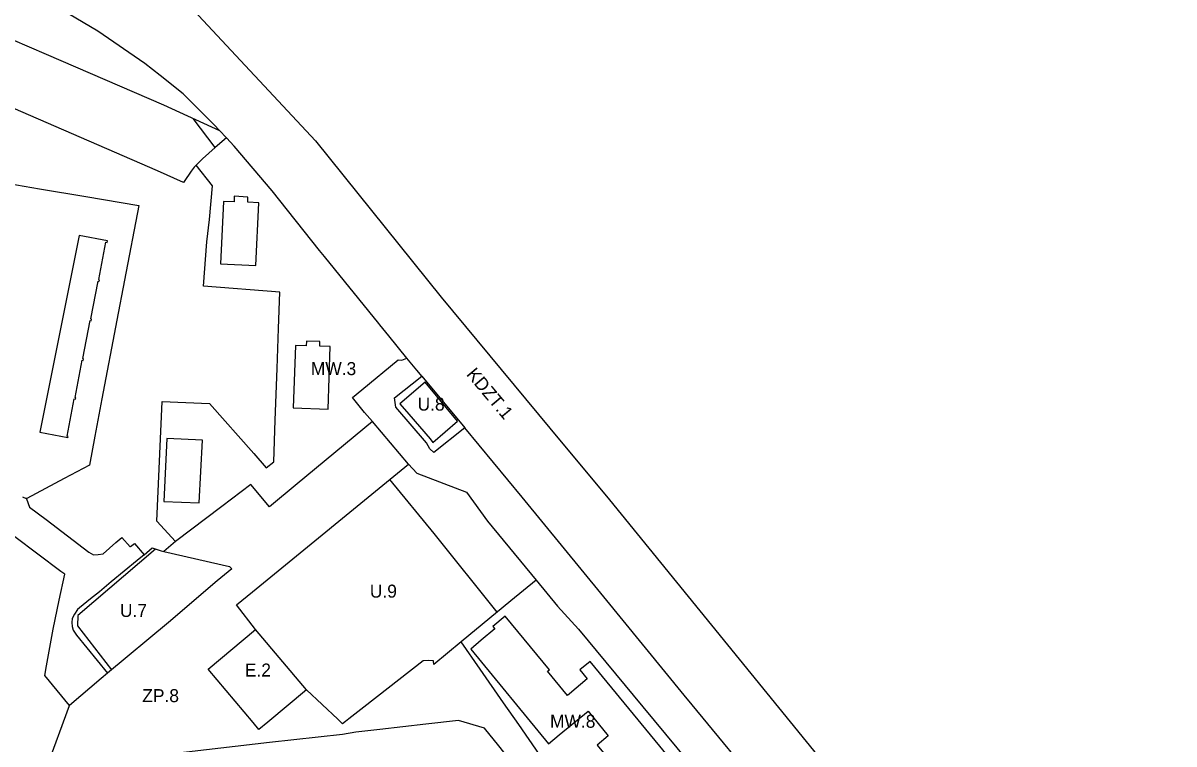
# Model space of a CAD drawing. Extents: x 7428689 to 7430424, y 5549101 to 5550539.
# Drawn here: x 7429899 to 7430341.5, y 5549954.9 to 5550232.1 of the extents above; entities that cross this region are included whole.
import ezdxf

# ---------------------------------------------------------------- set-up
doc = ezdxf.new("R2010")
doc.units = 0
for name, color, linetype in [('linie rozgraniczające', 7, 'Continuous'), ('nieprzekraczalne linie zabudowy', 7, 'Continuous'), ('obowiazujace linie zabudowy', 7, 'Continuous'), ('przeznaczenia terenów', 7, 'Continuous')]:
    doc.layers.add(name, color=color, linetype=linetype)

msp = doc.modelspace()

# ---------------------------------------------------------------- linework, layer by layer
at = {"layer": 'linie rozgraniczające'}
for points in [[(7429816.83, 5550334.12), (7429833.34, 5550323.51), (7429855.56, 5550306.27), (7429881.93, 5550290.04), (7429926.89, 5550263.18), (7429964.68, 5550236.86), (7430011.43, 5550186.87), (7430059.81, 5550126.71), (7430101.57, 5550076.38), (7430124.52, 5550048.84), (7430239.35, 5549907.74), (7430243.53, 5549902.67), (7430275.28, 5549864.05), (7430299.52, 5549835.73), (7430341.5, 5549786.7)], [(7429974.55, 5550190.8), (7429972.48, 5550192.99), (7429960.54, 5550204.88), (7429951.74, 5550211.88), (7429945.88, 5550216.54), (7429927.77, 5550228.95), (7429913.66, 5550237.27), (7429901.94, 5550242.49), (7429897.67, 5550244.65), (7429884.92, 5550250.06), (7429879.58, 5550252.11), (7429872.23, 5550253.14), (7429869.16, 5550253.7), (7429844.49, 5550258.25), (7429843.75, 5550257.92)], [(7429840.08, 5550249.7), (7429841.04, 5550249.22), (7429881.63, 5550231.45), (7429907.93, 5550220.14), (7429952.95, 5550200.66), (7429974.55, 5550190.8)], [(7429965.52, 5550177.42), (7429964.79, 5550176.7), (7429963.7, 5550175.14), (7429960.95, 5550171.21), (7429960.63, 5550170.77), (7429960.63, 5550170.77), (7429950.64, 5550175.25), (7429868.83, 5550210.74), (7429830.34, 5550227.16)], [(7429977.22, 5550187.97), (7429974.55, 5550190.8)], [(7429977.22, 5550187.97), (7429972.92, 5550184.19), (7429968.01, 5550179.86), (7429965.52, 5550177.42)], [(7430046.57, 5550103.3), (7430039.64, 5550111.84), (7430036.18, 5550116.11), (7430035.74, 5550116.65), (7430014.87, 5550142.37), (7430013, 5550144.71), (7429994.83, 5550167.53), (7429980.2, 5550184.81), (7429977.22, 5550187.97)], [(7429957.63, 5550032.81), (7429950.45, 5550040.61), (7429952.55, 5550086.64), (7429970.64, 5550085.84), (7429987.68, 5550066.58), (7429992.49, 5550061.14), (7429995.41, 5550063.45), (7429995.98, 5550079.47), (7429996.68, 5550099.33), (7429997.23, 5550114.66), (7429997.72, 5550128.64), (7429968.32, 5550130.9), (7429969.69, 5550147.97), (7429970.67, 5550156.63), (7429971.78, 5550169.49), (7429965.52, 5550177.42)], [(7429890.65, 5550170.87), (7429905.27, 5550168.41), (7429923.12, 5550165.39), (7429943.47, 5550161.94), (7429938, 5550133.23), (7429935.08, 5550117.93), (7429929.3, 5550087.66), (7429926.57, 5550073.31), (7429924.49, 5550062.1), (7429914.84, 5550057), (7429900.44, 5550049.34), (7429900.22, 5550049.26)], [(7430033.32, 5550078.87), (7430030.31, 5550082.41), (7430025.64, 5550088.17), (7430029.25, 5550091.14), (7430043.27, 5550102.67), (7430044.69, 5550102.51), (7430046.57, 5550103.3)], [(7430052.35, 5550096.35), (7430051.86, 5550096.93), (7430050.4, 5550098.69), (7430046.57, 5550103.3)], [(7430068.9, 5550076.43), (7430056.93, 5550066.95), (7430055.46, 5550068.36), (7430054.1, 5550070.73), (7430042.32, 5550084.38), (7430041.85, 5550088.03), (7430052.35, 5550096.35)], [(7430052.35, 5550096.35), (7430068.9, 5550076.43)], [(7430033.32, 5550078.87), (7430004.41, 5550054.97), (7429993.75, 5550046.17), (7429986.56, 5550054.72), (7429975.4, 5550046.27), (7429957.63, 5550032.81)], [(7430047.16, 5550062.55), (7430033.32, 5550078.87)], [(7430258.04, 5549845.58), (7430248.2, 5549857.63), (7430222.19, 5549889.25), (7430215.68, 5549897.16), (7430184.53, 5549935.61), (7430156.23, 5549969.99), (7430153.13, 5549973.76), (7430122.35, 5550011.53), (7430090.9, 5550049.78), (7430068.9, 5550076.43)], [(7429988.39, 5549998.93), (7429981.1, 5550008.49), (7429987.18, 5550013.47), (7430047.16, 5550062.55)], [(7430047.16, 5550062.55), (7430050.46, 5550059.05), (7430069.46, 5550051.75), (7430077.53, 5550040.58), (7430096.23, 5550017.94)], [(7429898.75, 5550050.01), (7429900.22, 5550049.26)], [(7429900.22, 5550049.26), (7429900.36, 5550049.19), (7429901.43, 5550046.02), (7429907.84, 5550041.19), (7429924.25, 5550028.63), (7429926.03, 5550027.7), (7429927.88, 5550027.77), (7429929.74, 5550028.1), (7429934.63, 5550032.4), (7429936.95, 5550034.32), (7429940.14, 5550030.72), (7429940.33, 5550030.88), (7429941.86, 5550032.07), (7429945.57, 5550027.67)], [(7429916.81, 5549969.68), (7429907.37, 5549981.28), (7429907.97, 5549984.97), (7429910.62, 5549999.1), (7429912.84, 5550010.27), (7429915.01, 5550020.22), (7429913.54, 5550021.3), (7429904.69, 5550027.9), (7429895.81, 5550034.62)], [(7429945.57, 5550027.67), (7429948.67, 5550030.31), (7429952.06, 5550029.17), (7429952.07, 5550029.17), (7429953.13, 5550028.93)], [(7429957.63, 5550032.81), (7429953.13, 5550028.93)], [(7429945.57, 5550027.67), (7429942.87, 5550025.42), (7429932.92, 5550017.22), (7429928.45, 5550013.44), (7429924.96, 5550010.69), (7429920.75, 5550007.3), (7429919.93, 5550006.59), (7429918.79, 5550004.89), (7429917.94, 5550003.17), (7429917.76, 5550001.64), (7429917.86, 5550000.05), (7429918.21, 5549998.68), (7429919.59, 5549996.77), (7429931.46, 5549982.14)], [(7429953.13, 5550028.93), (7429978.42, 5550023.18), (7429979.28, 5550022.22), (7429973.68, 5550017.66), (7429954.88, 5550001.69), (7429931.46, 5549982.14)], [(7430096.23, 5550017.94), (7430086.57, 5550010), (7430067.39, 5549994.23)], [(7430096.23, 5550017.94), (7430104.53, 5550007.9), (7430112.53, 5549999.04), (7430137.26, 5549969.22), (7430168.39, 5549931.68), (7430168.64, 5549931.38)], [(7430007.96, 5549975.79), (7429993.05, 5549963.37), (7429989.68, 5549960.56), (7429987.51, 5549963.14), (7429970.23, 5549983.76), (7429988.39, 5549998.93)], [(7430007.96, 5549975.79), (7429988.39, 5549998.93)], [(7430067.39, 5549994.23), (7430056.95, 5549985.45), (7430056.79, 5549986.97), (7430054.88, 5549987.05), (7430052.78, 5549986.95), (7430029.98, 5549969.1), (7430024.28, 5549964.64), (7430022.92, 5549963.57), (7430021.85, 5549962.74), (7430020.01, 5549964.46), (7430007.96, 5549975.79)], [(7430168.64, 5549931.38), (7430168.37, 5549930.61), (7430163.03, 5549927.09), (7430147.1, 5549927.18), (7430123.56, 5549927.32), (7430113.91, 5549933.66), (7430105.97, 5549938.87), (7430097.56, 5549950.93), (7430089.55, 5549962.42), (7430083.75, 5549970.74), (7430074.73, 5549983.7), (7430067.39, 5549994.23)], [(7429931.46, 5549982.14), (7429929.03, 5549980.11), (7429916.81, 5549969.68)], [(7429908.04, 5549945.59), (7429916.81, 5549969.68)], [(7430085.82, 5549949.33), (7430081.94, 5549954.22), (7430076.43, 5549961.08), (7430066.36, 5549963.92), (7430053.83, 5549962.51), (7430036.17, 5549960.52), (7430026.92, 5549959.51), (7430021.76, 5549958.62), (7429993.81, 5549955.51), (7429956.35, 5549951.19), (7429926.16, 5549947.7), (7429925.68, 5549947.31), (7429914.12, 5549946.03), (7429908.04, 5549945.59)]]:
    msp.add_lwpolyline(points, dxfattribs=at)
at = {"layer": 'nieprzekraczalne linie zabudowy'}
for points in [[(7429972.92, 5550184.19), (7429964.42, 5550195.42)], [(7430066.07, 5550079.05), (7430053.61, 5550094.05), (7430043.8, 5550085.68), (7430047.3, 5550081.67), (7430055.47, 5550072.21), (7430056.59, 5550070.89), (7430066.07, 5550079.05)], [(7430081.37, 5550005.72), (7430081.32, 5550005.68), (7430057.03, 5550035.86), (7430039.99, 5550056.68)], [(7429949.9, 5550029.9), (7429920.01, 5550004.29), (7429919.93, 5550000.31), (7429933.01, 5549983.44)]]:
    msp.add_lwpolyline(points, dxfattribs=at)
at = {"layer": 'obowiazujace linie zabudowy'}
for points in [[(7429976.05, 5550163.5), (7429974.92, 5550139.5), (7429988.52, 5550138.86), (7429989.62, 5550162.94), (7429985.45, 5550163.23), (7429985.46, 5550165.2), (7429980.21, 5550165.49), (7429980.19, 5550163.41), (7429976.05, 5550163.5)], [(7429905.44, 5550074.79), (7429916.22, 5550072.75), (7429916.31, 5550073.21), (7429915.99, 5550073.27), (7429918.7, 5550087.59), (7429919.21, 5550087.49), (7429919.32, 5550088.05), (7429918.99, 5550088.11), (7429921.71, 5550102.48), (7429922.13, 5550102.41), (7429922.25, 5550103.06), (7429922, 5550103.11), (7429924.77, 5550117.71), (7429925.24, 5550117.62), (7429925.37, 5550118.27), (7429925.1, 5550118.32), (7429927.85, 5550132.83), (7429928.2, 5550132.76), (7429928.33, 5550133.43), (7429928.12, 5550133.47), (7429930.84, 5550147.84), (7429931.35, 5550147.75), (7429931.48, 5550148.42), (7429920.61, 5550150.48), (7429905.44, 5550074.79)], [(7430017.14, 5550107.77), (7430013.11, 5550107.89), (7430013.1, 5550109.61), (7430007.93, 5550109.83), (7430007.83, 5550108.04), (7430003.69, 5550108.13), (7430002.91, 5550084.17), (7430016.37, 5550083.64), (7430017.14, 5550107.77)], [(7429954.25, 5550072.37), (7429953.09, 5550048.21), (7429966.67, 5550047.64), (7429967.97, 5550071.75), (7429954.25, 5550072.37)], [(7430100.69, 5549982.89), (7430101.39, 5549983.47), (7430084.39, 5550004.03), (7430079.67, 5550000.13), (7430080.43, 5549999.23), (7430075.15, 5549994.87), (7430071.11, 5549991.43), (7430101.06, 5549955.06), (7430105.13, 5549958.43), (7430116.3, 5549967.6), (7430124.01, 5549958.08), (7430119.73, 5549954.55), (7430140.42, 5549929.45), (7430144.69, 5549932.97), (7430149.92, 5549937.27), (7430150.46, 5549936.61), (7430155.07, 5549940.41), (7430117, 5549986.63), (7430113.09, 5549983.47), (7430115.92, 5549979.93), (7430109.04, 5549974.18), (7430108.31, 5549973.63), (7430100.69, 5549982.89)]]:
    msp.add_lwpolyline(points, dxfattribs=at)

# ---------------------------------------------------------------- texts
at = {"layer": 'przeznaczenia terenów'}
for s, p in [('MW.3', (7430009.64, 5550096.75)), ('U.8', (7430050.68, 5550083.1)), ('U.9', (7430032.33, 5550011.2)), ('U.7', (7429936.25, 5550003.77)), ('E.2', (7429984.27, 5549980.87)), ('ZP.8', (7429944.83, 5549971.03)), ('MW.8', (7430101.6, 5549961.19))]:
    msp.add_text(s, height=5, dxfattribs=at).set_placement(p)
msp.add_text('KDZT.1', height=5, rotation=310.0487, dxfattribs=at).set_placement((7430069.2, 5550096.92))

doc.saveas('drawing.dxf')
